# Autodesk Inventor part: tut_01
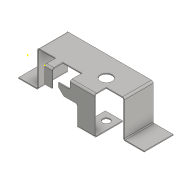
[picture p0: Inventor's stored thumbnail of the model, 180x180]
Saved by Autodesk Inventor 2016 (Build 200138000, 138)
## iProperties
Created: 2015-06
Part Number: tut_01
Material: Generic
Document SubType Name: Sheet Metal
Designer: Sandeep
Density: 1 g/cm^3
Sheet Metal Rule: Default_mm
Appearance: Default
Author: Sandeep
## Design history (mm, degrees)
node "Face1"
  sketch "Sketch1"
    geometry: L1 (0, 12)-(0, 44); L2 (0, 44)-(95, 44); L3 (95, 44)-(95, 12); L4 (95, 12)-(75, 12); L5 (75, 12)-(75, 0); L6 (75, 0)-(48, 0); L7 (48, 0)-(48, 18); L8 (48, 18)-(27, 18); L9 (27, 18)-(27, 0); L10 (27, 0)-(19, 0); L11 (19, 0)-(19, 12); L12 (19, 12)-(0, 12); L13 (0, 0)-(0, 88.508); L14 (0, 0)-(152.255, 0)
    constraints: 28 end point, 11 perpendicular, 4 point on line, 2 vertical, 1 horizontal
    dimensions: "d0" = 26 distance between parallel lines of L2 L8; "d1" = 19 distance between parallel lines of L13 L11; "d2" = 8 distance between parallel lines of L9 L11; "d3" = 32 distance between parallel lines of L12 L2; "d4" = 27 distance between parallel lines of L5 L7; "d5" = 20 distance between parallel lines of L3 L5; "d6" = 95 distance between parallel lines of L1 L3; "d7" = 44 distance between parallel lines of L6 L2
node "Contour Flange1"
  sketch "Sketch6"
    geometry: L1 (-75, 1)-(20, 1) reference; L2 (20, 1)-(20, -39); L3 (20, -39)-(42, -39); L4 (-75, 1)-(-75, -39); L5 (-75, -39)-(-97, -39); 1 further point
    constraints: 8 end point, 2 perpendicular, 2 vertical
    dimensions: "d9" = 40 distance of L1.end L2.end; "d10" = 22 distance of L2.end L3.end; "d20" = 40 distance of L1.start L4.end; "d21" = 22 distance of L4.end L5.end
sketch "Sketch7"
  geometry: 1 further point
sketch "Sketch8"
  geometry: 1 further point
node "Contour Flange2"
  sketch "Sketch9"
    geometry: L1 (0, 0)-(0, -40); L2 (0, -40)-(-22, -40); 1 further point
    constraints: 5 end point, 1 perpendicular, 1 vertical
    dimensions: "d22" = 22 distance of L1.end L2.end; "d23" = 40 distance of L1.start L1.end
node "Contour Flange3"
  sketch "Sketch10"
    geometry: L1 (0, 0)-(41, 0); L2 (41, 0)-(41, 30)
    constraints: 4 end point, 1 horizontal, 1 perpendicular
    dimensions: "d42" = 41 distance of L1.start L1.end; "d43" = 30 distance of L1.end L2.end
sketch "Sketch11"
  geometry: L1 (-3.447, 21)-(8, 21); L2 (8, 21)-(8, -7.777); L3 (8, -7.777)-(-3.447, -7.777); L4 (-3.447, -7.777)-(-3.447, 21); L5 (-21, 40)-(0, 40) reference; L6 (27, 38)-(27, 0) reference; 1 further point
  constraints: 8 end point, 2 parallel, 1 horizontal, 1 perpendicular
  dimensions: "d44" = 19 distance between parallel lines of L1 L5; "d45" = 19 distance between parallel lines of L6 L2
cut "Cut1" sketch "Sketch11" dims "d46" = 1 (= Thickness), "d47" = 0
node "Face2"
  sketch "Sketch12"
    geometry: L1 (0, -17)-(-13, -17); L2 (-13, -17)-(-13, -7); L3 (-13, -7)-(0, -7); L4 (0, 0)-(0, -17) reference; 1 further point
    constraints: 6 end point, 2 perpendicular, 1 horizontal, 1 point on line
    dimensions: "d54" = 13 distance between parallel lines of L2 L4; "d55" = 10 distance of L1.end L2.end
feature "Corner Round1" dims "d56" = 2
feature "Corner Chamfer1" dims "d57" = 6, "d58" = 6, angle "d59" = 45 deg
node "Flange1"
sketch "Sketch14"
  geometry: 1 further point
hole "Hole1" diameter "d72" = 13; stored, may be unused: countersink angle "d76" = 90 deg, drill point angle "d78" = 0 deg; dims "d70" = 9, "d71" = 22, "d73" = 6, "d74" = 4, "d75" = 2, "d77" = 1 (= Thickness)
hole "Hole2" diameter "d81" = 8; stored, may be unused: countersink angle "d85" = 90 deg, drill point angle "d87" = 0 deg; dims "d79" = 9, "d80" = 22, "d82" = 6, "d83" = 4, "d84" = 2, "d86" = 1 (= Thickness)
body "Solid1"
face "Plate1" dims "Thickness" = 1 (derived)
face "Plate2" dims "d11" = 1 (= BendReliefWidth), "d12" = 0.5 (= BendReliefDepth), "d13" = 2 (= MinimumRemnant), "d14" = 1 (= BendRadius), "d15" = 1 (= BendRadius), "d16" = 1, "d17" = 4 (= CornerReliefSize), "d18" = 1 (= GapSize), "d19" = 1 (= JacobiRadiusSize), "SeamGap" = 0.01, "Thickness" = 1 (derived)
bend "Bend1" dims "d11" = 1 (= BendReliefWidth), "d12" = 0.5 (= BendReliefDepth), "d13" = 2 (= MinimumRemnant), "d14" = 1 (= BendRadius), "d15" = 1 (= BendRadius), "d16" = 1, "SeamGap" = 0.01, "Thickness" = 1 (derived)
feature "Corner1" dims "d16" = 1, "d17" = 4 (= CornerReliefSize), "d18" = 1 (= GapSize), "d19" = 1 (= JacobiRadiusSize)
face "Plate3" dims "d24" = 1 (= BendReliefWidth), "d25" = 0.5 (= BendReliefDepth), "d26" = 2 (= MinimumRemnant), "d27" = 1 (= BendRadius), "d28" = 1 (= BendRadius), "d29" = 1, "d30" = 4 (= CornerReliefSize), "d31" = 1 (= GapSize), "d32" = 1 (= JacobiRadiusSize), "SeamGap" = 0.01, "Thickness" = 1 (derived)
bend "Bend2" dims "d24" = 1 (= BendReliefWidth), "d25" = 0.5 (= BendReliefDepth), "d26" = 2 (= MinimumRemnant), "d27" = 1 (= BendRadius), "d28" = 1 (= BendRadius), "d29" = 1, "SeamGap" = 0.01, "Thickness" = 1 (derived)
feature "Corner2" dims "d29" = 1, "d30" = 4 (= CornerReliefSize), "d31" = 1 (= GapSize), "d32" = 1 (= JacobiRadiusSize)
face "Plate4" dims "d33" = 1 (= BendReliefWidth), "d34" = 0.5 (= BendReliefDepth), "d35" = 2 (= MinimumRemnant), "d36" = 1 (= BendRadius), "d37" = 1 (= BendRadius), "d38" = 1, "d39" = 4 (= CornerReliefSize), "d40" = 1 (= GapSize), "d41" = 1 (= JacobiRadiusSize), "SeamGap" = 0.01, "Thickness" = 1 (derived)
bend "Bend3" dims "d33" = 1 (= BendReliefWidth), "d34" = 0.5 (= BendReliefDepth), "d35" = 2 (= MinimumRemnant), "d36" = 1 (= BendRadius), "d37" = 1 (= BendRadius), "d38" = 1, "SeamGap" = 0.01, "Thickness" = 1 (derived)
feature "Corner3" dims "d38" = 1, "d39" = 4 (= CornerReliefSize), "d40" = 1 (= GapSize), "d41" = 1 (= JacobiRadiusSize)
face "Plate5" dims "d49" = 1 (= BendRadius), "d50" = 1 (= BendReliefWidth), "d52" = 2 (= MinimumRemnant), "Thickness" = 1 (derived)
bend "Bend4" dims "d49" = 1 (= BendRadius), "d50" = 1 (= BendReliefWidth), "d51" = 0.5 (= BendReliefDepth), "d52" = 2 (= MinimumRemnant), "d53" = 1 (= BendRadius), "SeamGap" = 0.01, "Thickness" = 1 (derived)
sketch "Sketch13"
  geometry: L1 through (-4, 0) direction (1, 2.83e-18); L2 through (0, 9.5) direction (1.45e-17, 1); L3 (0, 19)-(-8, 19); L4 (-8, 19)-(-8, 0)
  constraints: 6 end point, 1 horizontal, 1 perpendicular, 1 vertical
face "Plate6" dims "d60" = 1 (= BendReliefWidth), "d61" = 0.5 (= BendReliefDepth), "d62" = 2 (= MinimumRemnant), "d63" = 1 (= BendRadius), "d64" = 19, "d65" = 90 deg, "d66" = 1 (= BendRadius), "d67" = 4 (= CornerReliefSize), "d68" = 1 (= GapSize), "d69" = 1 (= JacobiRadiusSize), "SeamGap" = 0.01, "Thickness" = 1 (derived)
bend "Bend5" dims "d60" = 1 (= BendReliefWidth), "d61" = 0.5 (= BendReliefDepth), "d62" = 2 (= MinimumRemnant), "d63" = 1 (= BendRadius), "d64" = 19, "d65" = 90 deg, "d66" = 1 (= BendRadius), "SeamGap" = 0.01, "Thickness" = 1 (derived)
feature "Corner4" dims "d64" = 19, "d65" = 90 deg, "d67" = 4 (= CornerReliefSize), "d68" = 1 (= GapSize), "d69" = 1 (= JacobiRadiusSize)
other parameters: "BendRadius" = 1 (= Thickness), "BendReliefWidth" = 1 (= Thickness), "BendReliefDepth" = 0.5 (= 0.5 x Thickness), "CornerReliefSize" = 4 (= 4 x Thickness), "MinimumRemnant" = 2 (= 2 x Thickness), "TransitionRadius" = 1 (= BendRadius), "JacobiRadiusSize" = 1 (= BendRadius), "GapSize" = 1 (= Thickness), "d8" = 1 (= BendRadius)
